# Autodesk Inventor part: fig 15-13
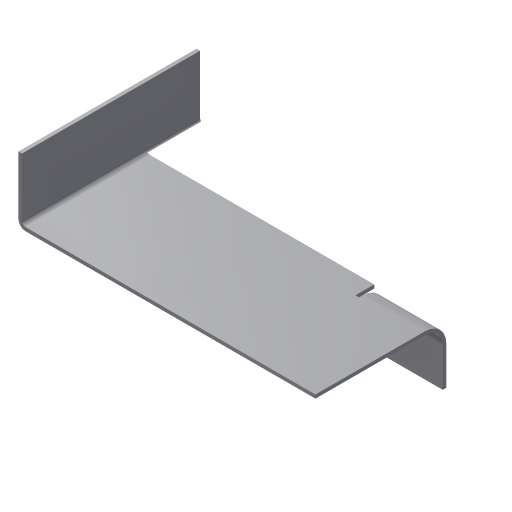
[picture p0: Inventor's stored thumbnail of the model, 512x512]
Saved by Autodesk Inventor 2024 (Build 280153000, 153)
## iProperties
Shininess: 77.0
Angle Display Precision: 2
Document Length Units: 11269
Document Angle Units: 11279
Document Time Units: 11290
Document Mass Units: 11283
Document Length Units Precision: 3
Document Angle Units Precision: 2
Created: 2002-04
Part Number: fig 15-13
Material: Aluminum-6061
Document SubType Name: Sheet Metal
Density: 1 g/cm^3
Sheet Metal Rule: Default
Appearance: Aluminum - Flat-1
Density: 0.0
Volumn: 0.0
Area: 0.0
PropertySet Name: Model Information
Control State: 0
Master: False
Checked Out: False
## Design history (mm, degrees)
node "Face1"
  sketch "Sketch1"
    geometry: L1 (-49.559, 19.574)-(-49.559, -30.426); L2 (-49.559, -30.426)-(50.441, -30.426); L3 (50.441, -30.426)-(50.441, 19.574); L4 (50.441, 19.574)-(32.941, 19.574); L5 (32.941, 19.574)-(32.941, 4.574); L6 (32.941, 4.574)-(-32.059, 4.574); L7 (-32.059, 4.574)-(-32.059, 19.574); L8 (-32.059, 19.574)-(-49.559, 19.574)
    constraints: 16 end point, 6 parallel, 2 equal length, 1 perpendicular, 1 vertical
    dimensions: "d0" = 100 distance of L1.end L2.end; "d1" = 65 distance of L5.end L6.end; "d2" = 15 distance of L6.end L7.end; "d3" = 50 distance of L1.start L1.end
feature "Fold2" dims "d8" = 1 (= BendRadius), "d9" = 90 deg, "d10" = 1 (= BendRadius), "d14" = 1 (= BendReliefWidth), "d15" = 0.5 (= BendReliefDepth), "d16" = 2 (= MinimumRemnant), "d20" = 1 (= Thickness), "SeamGap" = 0.01
feature "Fold3" dims "d11" = 1 (= BendRadius), "d12" = 90 deg, "d13" = 5, "d17" = 1 (= BendReliefWidth), "d18" = 1, "d19" = 2 (= MinimumRemnant), "d20" = 1 (= Thickness), "SeamGap" = 0.01
body "Solid1"
sketch "Sketch2"
  geometry: L1 (100, 0)-(0, 0) reference; L2 (17.5, 50)-(17.5, 35) reference; L3 (82.5, 50)-(82.5, 0)
  constraints: 2 end point, 1 parallel, 1 point on line
face "Plate1" dims "d20" = 1 (= Thickness)
sketch "Sketch3"
  geometry: L1 (81.369, -50)-(0, -50) reference; L2 (17.5, 0)-(17.5, -50)
  constraints: 2 end point, 1 perpendicular, 1 point on line
sketch "Sketch4"
  geometry: L1 (17.5, 0)-(17.5, -50) reference; L2 (-63.869, -15)-(0, -15) reference; L3 (0, -15)-(17.5, -15)
  constraints: 2 end point, 1 collinear, 1 point on line
other parameters: "Thickness" = 1, "BendRadius" = 1 (= Thickness), "BendReliefWidth" = 1 (= Thickness), "BendReliefDepth" = 0.5 (= 0.5 x Thickness), "CornerReliefSize" = 4 (= 4 x Thickness), "MinimumRemnant" = 2 (= 2 x Thickness), "TransitionRadius" = 1 (= BendRadius), "d4" = 1 (= BendRadius), "JacobiRadiusSize" = 1 (= Thickness), "GapSize" = 1 (= Thickness)
